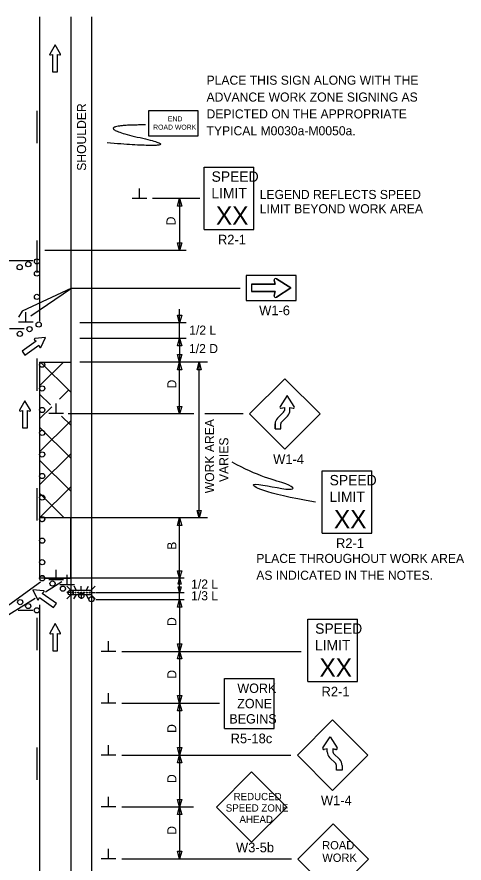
# Model space of a CAD drawing. Extents: x 16750 to 18296, y 5932 to 6919.
# Drawn here: x 17082 to 17427, y 6265 to 6918 of the extents above; entities that cross this region are included whole.
import ezdxf

# ---------------------------------------------------------------- set-up
doc = ezdxf.new("R2010")
doc.units = 0
for name, color, linetype in [('BORDER', 7, 'Continuous'), ('MT_SCRATCH_LEVEL_A', 7, 'Continuous'), ('MT_SCRATCH_LEVEL_E', 7, 'Continuous'), ('MT_STAGE_1A_NOTES', 7, 'Continuous'), ('PAVT_EDGE_EX', 7, 'Continuous'), ('TRAFFIC_SIGNS_PR', 7, 'Continuous'), ('TYPICAL_EX', 7, 'Continuous'), ('TYPICAL_TEXT_DIMEN_EX', 7, 'Continuous'), ('TYPICAL_TEXT_DIMEN_PR', 7, 'Continuous')]:
    doc.layers.add(name, color=color, linetype=linetype)

msp = doc.modelspace()

# ---------------------------------------------------------------- linework, layer by layer
at = {"layer": 'BORDER'}
msp.add_line((17123.59, 6917.57), (17123.59, 6063.18), dxfattribs=at)
at = {"layer": 'MT_SCRATCH_LEVEL_A'}
for p, q in [((17099.59, 6917.57), (17099.59, 6682.86)), ((17099.59, 6651.4), (17123.59, 6651.4)), ((17099.59, 6651.4), (17099.59, 6484.67)), ((17099.59, 6633.05), (17117.94, 6651.4)), ((17123.59, 6628.14), (17100.33, 6651.4)), ((17114.89, 6622.89), (17121.86, 6629.87)), ((17107.95, 6618.33), (17099.59, 6626.69)), ((17099.59, 6607.59), (17109.02, 6617.02)), ((17099.59, 6582.14), (17123.59, 6606.14)), ((17123.59, 6602.69), (17116.62, 6609.66)), ((17123.59, 6577.23), (17099.59, 6601.23)), ((17099.59, 6556.68), (17123.59, 6580.68)), ((17123.59, 6551.78), (17099.59, 6575.78)), ((17099.59, 6531.23), (17123.59, 6555.23)), ((17118.68, 6531.23), (17099.59, 6550.32)), ((17099.59, 6464.33), (17099.59, 6063.18))]:
    msp.add_line(p, q, dxfattribs=at)
for points in [[(17097.59, 6845.22), (17097.59, 6820.22)], [(17097.59, 6745.22), (17097.59, 6720.22)], [(17097.59, 6654.22), (17097.59, 6629.22)], [(17097.59, 6554.22), (17097.59, 6529.22)], [(17097.59, 6454.22), (17097.59, 6429.22)], [(17097.59, 6354.22), (17097.59, 6329.22)]]:
    msp.add_lwpolyline(points, dxfattribs=at)
at = {"layer": 'MT_SCRATCH_LEVEL_E'}
for p, q in [((17111.52, 6896.14), (17107.41, 6888.9)), ((17111.52, 6896.14), (17107.41, 6888.9)), ((17115.67, 6888.9), (17111.52, 6896.14)), ((17115.67, 6888.9), (17111.52, 6896.14)), ((17107.89, 6888.22), (17109.67, 6888.53)), ((17107.89, 6888.22), (17109.67, 6888.53)), ((17109.67, 6888.53), (17109.67, 6875.27)), ((17109.67, 6888.53), (17109.67, 6875.27)), ((17113.41, 6875.27), (17113.41, 6888.53)), ((17113.41, 6888.53), (17115.19, 6888.22)), ((17113.41, 6875.27), (17113.41, 6888.53)), ((17113.41, 6888.53), (17115.19, 6888.22)), ((17109.67, 6875.27), (17113.41, 6875.27)), ((17109.67, 6875.27), (17113.41, 6875.27)), ((17095.68, 6668.7), (17096.95, 6667.42)), ((17095.68, 6668.7), (17096.95, 6667.42)), ((17104.25, 6670.26), (17095.96, 6669.49)), ((17104.25, 6670.26), (17095.96, 6669.49)), ((17100.69, 6662.72), (17104.25, 6670.26)), ((17100.69, 6662.72), (17104.25, 6670.26)), ((17096.95, 6667.42), (17086.08, 6659.83)), ((17096.95, 6667.42), (17086.08, 6659.83)), ((17088.23, 6656.77), (17099.09, 6664.36)), ((17088.23, 6656.77), (17099.09, 6664.36)), ((17099.09, 6664.36), (17099.85, 6662.72)), ((17099.09, 6664.36), (17099.85, 6662.72)), ((17086.08, 6659.83), (17088.23, 6656.77)), ((17086.08, 6659.83), (17088.23, 6656.77)), ((17088.36, 6621.59), (17084.25, 6614.35)), ((17088.36, 6621.59), (17084.25, 6614.35)), ((17092.5, 6614.35), (17088.36, 6621.59)), ((17092.5, 6614.35), (17088.36, 6621.59)), ((17084.73, 6613.66), (17086.51, 6613.98)), ((17084.73, 6613.66), (17086.51, 6613.98)), ((17086.51, 6613.98), (17086.51, 6600.72)), ((17086.51, 6613.98), (17086.51, 6600.72)), ((17090.25, 6600.72), (17090.25, 6613.98)), ((17090.25, 6613.98), (17092.03, 6613.66)), ((17090.25, 6600.72), (17090.25, 6613.98)), ((17090.25, 6613.98), (17092.03, 6613.66)), ((17086.51, 6600.72), (17090.25, 6600.72)), ((17086.51, 6600.72), (17090.25, 6600.72)), ((17094.4, 6475.74), (17097.98, 6468.22)), ((17102.71, 6474.99), (17094.4, 6475.74)), ((17094.4, 6475.74), (17097.98, 6468.22)), ((17102.71, 6474.99), (17094.4, 6475.74)), ((17101.72, 6472.93), (17103, 6474.21)), ((17101.72, 6472.93), (17103, 6474.21)), ((17112.59, 6465.34), (17101.72, 6472.93)), ((17112.59, 6465.34), (17101.72, 6472.93)), ((17098.82, 6468.23), (17099.58, 6469.86)), ((17098.82, 6468.23), (17099.58, 6469.86)), ((17099.58, 6469.86), (17110.45, 6462.27)), ((17099.58, 6469.86), (17110.45, 6462.27)), ((17110.45, 6462.27), (17112.59, 6465.34)), ((17110.45, 6462.27), (17112.59, 6465.34)), ((17111.61, 6449.74), (17107.5, 6442.5)), ((17111.61, 6449.74), (17107.5, 6442.5)), ((17115.76, 6442.5), (17111.61, 6449.74)), ((17115.76, 6442.5), (17111.61, 6449.74)), ((17107.99, 6441.82), (17109.76, 6442.13)), ((17107.99, 6441.82), (17109.76, 6442.13)), ((17109.76, 6442.13), (17109.76, 6428.88)), ((17109.76, 6442.13), (17109.76, 6428.88)), ((17113.5, 6428.88), (17113.5, 6442.13)), ((17113.5, 6442.13), (17115.28, 6441.82)), ((17113.5, 6428.88), (17113.5, 6442.13)), ((17113.5, 6442.13), (17115.28, 6441.82)), ((17109.76, 6428.88), (17113.5, 6428.88)), ((17109.76, 6428.88), (17113.5, 6428.88))]:
    msp.add_line(p, q, dxfattribs=at)
for centre, start, end in [((17107.82, 6888.68), 150.42484, 279.96381), ((17107.82, 6888.68), 150.42484, 279.96381), ((17115.26, 6888.68), 260.03619, 29.77312), ((17115.26, 6888.68), 260.03619, 29.77312), ((17096.01, 6669.02), 95.35605, 224.89502), ((17096.01, 6669.02), 95.35605, 224.89502), ((17100.27, 6662.93), 204.96741, 334.70433), ((17100.27, 6662.93), 204.96741, 334.70433), ((17084.65, 6614.12), 150.42484, 279.96381), ((17084.65, 6614.12), 150.42484, 279.96381), ((17092.09, 6614.12), 260.03619, 29.77312), ((17092.09, 6614.12), 260.03619, 29.77312), ((17102.66, 6474.53), 315.10498, 84.84191), ((17102.66, 6474.53), 315.10498, 84.84191), ((17098.4, 6468.43), 205.49363, 335.0326), ((17098.4, 6468.43), 205.49363, 335.0326), ((17107.91, 6442.28), 150.42484, 279.96381), ((17107.91, 6442.28), 150.42484, 279.96381), ((17115.35, 6442.28), 260.03619, 29.77312), ((17115.35, 6442.28), 260.03619, 29.77312)]:
    msp.add_arc(centre, 0.463, start, end, dxfattribs=at)
at = {"layer": 'MT_STAGE_1A_NOTES'}
for p, q in [((17101.26, 6513.92), (17101.23, 6513.89)), ((17101.36, 6512.6), (17101.35, 6512.54))]:
    msp.add_line(p, q, dxfattribs=at)
for points in [[(17099.82, 6531.23), (17099.59, 6531.23), (17099.59, 6484.67), (17099.61, 6484.67)], [(17103.61, 6484.67), (17112.33, 6484.67), (17120.92, 6484.67), (17123.59, 6484.67), (17123.59, 6531.23), (17103.41, 6531.23)]]:
    msp.add_lwpolyline(points, dxfattribs=at)
for centre, start, end in [((17101.61, 6530.34), 153.67259, 214.93121), ((17101.61, 6530.34), 214.93121, 26.32741), ((17101.61, 6484.67), 0, 180)]:
    msp.add_arc(centre, 2, start, end, dxfattribs=at)
at = {"layer": 'PAVT_EDGE_EX'}
msp.add_line((17139.59, 6917.57), (17139.59, 6063.18), dxfattribs=at)
at = {"layer": 'TRAFFIC_SIGNS_PR'}
for p, q in [((17226.43, 6801.61), (17264.83, 6801.61)), ((17226.43, 6753.61), (17226.43, 6801.61)), ((17264.83, 6753.61), (17264.83, 6801.61)), ((17226.43, 6753.61), (17264.83, 6753.61)), ((17281.31, 6711.41), (17280.47, 6714.47)), ((17282.15, 6715.71), (17293.31, 6708.61)), ((17262.91, 6711.41), (17281.31, 6711.41)), ((17262.91, 6711.41), (17262.91, 6705.81)), ((17293.31, 6708.61), (17282.15, 6701.51)), ((17281.31, 6705.81), (17262.91, 6705.81)), ((17280.47, 6702.75), (17281.31, 6705.81)), ((17288.66, 6638.55), (17261.51, 6611.4)), ((17315.81, 6611.4), (17288.66, 6638.55)), ((17261.51, 6611.4), (17288.66, 6584.25)), ((17283, 6608.15), (17287.72, 6612.86)), ((17287.72, 6612.86), (17283, 6608.15)), ((17286.05, 6605.1), (17290.77, 6609.81)), ((17286.06, 6605.1), (17290.77, 6609.81)), ((17288.66, 6584.25), (17315.81, 6611.4)), ((17281.14, 6600.03), (17281.14, 6603.73)), ((17285.45, 6600.03), (17285.45, 6603.73)), ((17281.14, 6600.03), (17285.45, 6600.03)), ((17317.41, 6567.51), (17355.81, 6567.51)), ((17317.41, 6519.51), (17317.41, 6567.51)), ((17355.81, 6519.51), (17355.81, 6567.51)), ((17317.41, 6519.51), (17355.81, 6519.51)), ((17120.69, 6478.54), (17123.51, 6475.72)), ((17123.51, 6473.69), (17120.69, 6473.69)), ((17125.15, 6473.69), (17125.15, 6473.69)), ((17127.78, 6475.72), (17126.15, 6478.54)), ((17127.32, 6473.69), (17127.32, 6473.69)), ((17129.49, 6473.69), (17129.49, 6473.69)), ((17131.59, 6475.72), (17131.59, 6478.54)), ((17131.67, 6473.69), (17131.67, 6473.69)), ((17133.84, 6473.69), (17133.84, 6473.69)), ((17135.73, 6475.72), (17137.36, 6478.54)), ((17136.02, 6473.69), (17136.02, 6473.69)), ((17138.19, 6473.69), (17138.19, 6473.69)), ((17139.68, 6475.72), (17142.5, 6478.54)), ((17139.68, 6473.69), (17142.5, 6473.69)), ((17120.69, 6468.84), (17123.51, 6471.65)), ((17126.12, 6468.83), (17127.75, 6471.65)), ((17131.59, 6471.65), (17131.59, 6468.83)), ((17137.38, 6468.83), (17135.75, 6471.65)), ((17139.68, 6471.65), (17142.5, 6468.83)), ((17306.27, 6453.07), (17344.67, 6453.07)), ((17306.27, 6405.07), (17306.27, 6453.07)), ((17344.67, 6405.07), (17344.67, 6453.07)), ((17242.07, 6368.94), (17242.07, 6407.34)), ((17242.07, 6407.34), (17280.47, 6407.34)), ((17280.47, 6368.94), (17280.47, 6407.34)), ((17306.27, 6405.07), (17344.67, 6405.07)), ((17298.32, 6348.33), (17325.47, 6375.48)), ((17352.63, 6348.33), (17325.47, 6375.48)), ((17242.07, 6368.94), (17280.47, 6368.94)), ((17330.95, 6344.87), (17326.23, 6349.58)), ((17326.23, 6349.58), (17330.95, 6344.87)), ((17325.47, 6321.18), (17298.32, 6348.33)), ((17327.89, 6341.81), (17323.18, 6346.53)), ((17327.89, 6341.81), (17323.18, 6346.53)), ((17352.63, 6348.33), (17325.47, 6321.18)), ((17263.09, 6335.45), (17235.93, 6308.29)), ((17290.24, 6308.29), (17263.09, 6335.45)), ((17235.93, 6308.29), (17263.09, 6281.14)), ((17263.09, 6281.14), (17290.24, 6308.29)), ((17325.89, 6295.29), (17298.7, 6268.1)), ((17353.07, 6268.1), (17325.89, 6295.29)), ((17298.7, 6268.1), (17325.89, 6240.91)), ((17325.89, 6240.91), (17353.07, 6268.1))]:
    msp.add_line(p, q, dxfattribs=at)
for points in [[(17183.54, 6825.92), (17221.94, 6825.92), (17221.94, 6845.12), (17183.54, 6845.12)], [(17258.91, 6699.01), (17297.31, 6699.01), (17297.31, 6718.21), (17258.91, 6718.21)], [(17139.45, 6471.89), (17123.74, 6471.89), (17123.74, 6475.49), (17139.45, 6475.49)]]:
    msp.add_lwpolyline(points, close=True, dxfattribs=at)
for points in [[(17280.47, 6714.47), (17281.31, 6711.41), (17262.91, 6711.41), (17262.91, 6705.81), (17281.31, 6705.81), (17280.47, 6702.75)], [(17282.15, 6701.51), (17293.31, 6708.61), (17282.15, 6715.71)], [(17295.92, 6617.14), (17290.44, 6625.75), (17284.96, 6617.14)], [(17295.92, 6617.14), (17290.44, 6625.75), (17284.96, 6617.14)], [(17285.92, 6615.84), (17288.28, 6616.49), (17288.28, 6614.19)], [(17285.92, 6615.84), (17286.75, 6616.07), (17288.28, 6616.49), (17288.28, 6614.19)], [(17292.59, 6614.12), (17292.6, 6616.49), (17294.96, 6615.84)], [(17281.13, 6603.73), (17281.14, 6600.03), (17285.45, 6600.03), (17285.45, 6603.73)], [(17318.02, 6353.86), (17323.51, 6362.47), (17328.99, 6353.85)], [(17318.03, 6353.85), (17323.51, 6362.47), (17328.99, 6353.85)], [(17321.36, 6350.84), (17321.35, 6353.21), (17318.99, 6352.56)], [(17321.36, 6350.84), (17321.35, 6353.21), (17318.99, 6352.56)], [(17328.03, 6352.56), (17325.67, 6353.21), (17325.67, 6350.91)], [(17328.03, 6352.56), (17327.19, 6352.79), (17325.67, 6353.21), (17325.67, 6350.91)], [(17332.81, 6340.45), (17332.81, 6336.75), (17328.5, 6336.75), (17328.5, 6340.45)]]:
    msp.add_lwpolyline(points, dxfattribs=at)
for centre, radius in [((17090.92, 6726.9), 2), ((17097.59, 6729.05), 2), ((17084.26, 6724.59), 2), ((17097.59, 6719.69), 2), ((17097.59, 6701.69), 2), ((17098.93, 6680.39), 2), ((17084.45, 6673.15), 2), ((17091.88, 6676.87), 2), ((17101.61, 6649.4), 2), ((17101.61, 6631.09), 2), ((17101.61, 6614.48), 2), ((17101.61, 6596.79), 2), ((17101.61, 6580.18), 2), ((17101.61, 6563.56), 2), ((17101.61, 6546.95), 2), ((17101.61, 6530.34), 2), ((17101.61, 6513.73), 2), ((17101.61, 6497.12), 2), ((17101.61, 6484.67), 2), ((17109.61, 6480.67), 2), ((17117.61, 6476.67), 2), ((17123.59, 6473.69), 2), ((17125.17, 6473.69), 0.379), ((17127.32, 6473.69), 0.379), ((17129.49, 6473.69), 0.379), ((17131.81, 6471.27), 2), ((17131.67, 6473.69), 0.379), ((17133.84, 6473.69), 0.379), ((17136.01, 6473.69), 0.379), ((17138.19, 6473.69), 0.379), ((17084.65, 6466.32), 2), ((17139.57, 6468.56), 2), ((17090.87, 6463.28), 2), ((17097.46, 6460), 2)]:
    msp.add_circle(centre, radius, dxfattribs=at)
for centre, radius, start, end in [((17281.55, 6714.76), 1.12, 57.53038, 195.32692), ((17281.55, 6714.76), 1.12, 57.53038, 195.32692), ((17281.55, 6702.45), 1.12, 164.67308, 302.46962), ((17281.55, 6702.45), 1.12, 164.67308, 302.46963), ((17285.69, 6616.67), 0.864, 147.52044, 285.3986), ((17285.69, 6616.67), 0.866, 147.52881, 285.38519), ((17295.19, 6616.68), 0.866, 254.67989, 32.28036), ((17286.43, 6614.19), 1.85, 314.21254, 0), ((17286.43, 6614.19), 1.85, 314.2123, 0.1238), ((17286.43, 6614.19), 6.17, 314.21254, 359.38189), ((17286.43, 6614.19), 6.17, 314.76872, 359.37555), ((17287.3, 6603.73), 6.17, 134.21254, 180), ((17287.3, 6603.73), 6.17, 134.21254, 180), ((17287.3, 6603.73), 6.17, 134.21172, 180), ((17287.3, 6603.73), 1.85, 132.37199, 180), ((17287.3, 6603.73), 1.85, 134.21254, 180), ((17318.76, 6353.39), 0.866, 147.7292, 285.31719), ((17318.76, 6353.39), 0.866, 147.71964, 285.32011), ((17308.91, 6359.65), 10.8, 327.53351, 327.54311), ((17321.84, 6342.14), 10.8, 105.31922, 105.32004), ((17327.52, 6350.91), 6.17, 180.61811, 225.78746), ((17327.52, 6350.91), 6.17, 180.62445, 225.23128), ((17327.52, 6350.91), 1.85, 180, 225.78746), ((17327.52, 6350.91), 1.85, 179.8762, 225.7877), ((17328.26, 6353.39), 0.866, 254.61481, 32.47119), ((17326.64, 6340.45), 6.17, 0, 45.78828), ((17326.64, 6340.45), 1.85, 0, 47.62801)]:
    msp.add_arc(centre, radius, start, end, dxfattribs=at)
msp.add_open_spline([(17181.19, 6834.28), (17133.95, 6834.28), (17218.98, 6814.94), (17151.64, 6820.43)], degree=2, dxfattribs=at)
at = {"layer": 'TYPICAL_EX'}
for p, q in [((17176.71, 6777.47), (17176.71, 6785.26)), ((17182.34, 6777.47), (17171.09, 6777.47)), ((17088.96, 6682.12), (17088.96, 6689.91)), ((17094.59, 6682.12), (17083.34, 6682.12)), ((17087.66, 6677.17), (17076.41, 6677.17)), ((17112.33, 6611.74), (17112.33, 6619.53)), ((17117.95, 6611.74), (17106.7, 6611.74)), ((17112.33, 6483.42), (17112.33, 6491.2)), ((17120.92, 6479.56), (17120.92, 6487.34)), ((17117.95, 6483.42), (17106.7, 6483.42)), ((17126.55, 6479.56), (17115.3, 6479.56)), ((17152.71, 6428.36), (17152.71, 6436.14)), ((17158.34, 6428.36), (17147.09, 6428.36)), ((17152.71, 6388.36), (17152.71, 6396.14)), ((17158.34, 6388.36), (17147.09, 6388.36)), ((17152.71, 6348.36), (17152.71, 6356.14)), ((17158.34, 6348.36), (17147.09, 6348.36)), ((17152.71, 6308.36), (17152.71, 6316.14)), ((17158.34, 6308.36), (17147.09, 6308.36)), ((17152.71, 6268.36), (17152.71, 6276.14)), ((17158.34, 6268.36), (17147.09, 6268.36))]:
    msp.add_line(p, q, dxfattribs=at)
at = {"layer": 'TYPICAL_TEXT_DIMEN_PR'}
for p, q in [((17223.13, 6777.47), (17186.59, 6777.47)), ((17206.02, 6771.61), (17207.59, 6777.47)), ((17207.59, 6777.47), (17209.16, 6771.61)), ((17207.59, 6777.47), (17207.59, 6737.47)), ((17207.59, 6771.61), (17206.02, 6771.61)), ((17209.16, 6771.61), (17207.59, 6771.61)), ((17207.59, 6737.47), (17206.02, 6743.34)), ((17206.02, 6743.34), (17207.59, 6743.34)), ((17207.59, 6737.47), (17206.02, 6743.34)), ((17206.02, 6743.34), (17207.59, 6743.34)), ((17207.59, 6743.34), (17209.16, 6743.34)), ((17209.16, 6743.34), (17207.59, 6737.47)), ((17207.59, 6743.34), (17209.16, 6743.34)), ((17209.16, 6743.34), (17207.59, 6737.47)), ((17212.59, 6737.47), (17103.65, 6737.47)), ((16962.49, 6729.72), (17094.41, 6729.72)), ((17124.22, 6708.37), (17086.08, 6690.64)), ((17092.76, 6687.09), (17124.22, 6708.37)), ((17124.22, 6708.37), (17254.22, 6708.37)), ((17086.08, 6690.64), (17083.35, 6686)), ((17207.59, 6669.72), (17207.59, 6692.26)), ((17212.59, 6681.72), (17130.55, 6681.72)), ((17207.59, 6681.72), (17206.02, 6687.58)), ((17206.02, 6687.58), (17207.59, 6687.58)), ((17207.59, 6687.58), (17209.16, 6687.58)), ((17209.16, 6687.58), (17207.59, 6681.72)), ((17212.59, 6669.72), (17130.55, 6669.72)), ((17206.02, 6663.86), (17207.59, 6669.72)), ((17207.59, 6669.72), (17209.16, 6663.86)), ((17207.59, 6669.72), (17207.59, 6651.4)), ((17207.59, 6663.86), (17206.02, 6663.86)), ((17209.16, 6663.86), (17207.59, 6663.86)), ((17207.59, 6651.4), (17206.02, 6657.26)), ((17206.02, 6657.26), (17207.59, 6657.26)), ((17207.59, 6657.26), (17209.16, 6657.26)), ((17209.16, 6657.26), (17207.59, 6651.4)), ((17229.13, 6651.4), (17130.55, 6651.4)), ((17206.02, 6645.54), (17207.59, 6651.4)), ((17207.59, 6611.4), (17207.59, 6651.4)), ((17207.59, 6651.4), (17209.16, 6645.54)), ((17221.02, 6645.54), (17222.59, 6651.4)), ((17222.59, 6531.23), (17222.59, 6651.4)), ((17222.59, 6651.4), (17224.16, 6645.54)), ((17207.59, 6645.54), (17206.02, 6645.54)), ((17209.16, 6645.54), (17207.59, 6645.54)), ((17222.59, 6645.54), (17221.02, 6645.54)), ((17224.16, 6645.54), (17222.59, 6645.54)), ((17207.59, 6611.4), (17206.02, 6617.26)), ((17206.02, 6617.26), (17207.59, 6617.26)), ((17207.59, 6617.26), (17209.16, 6617.26)), ((17209.16, 6617.26), (17207.59, 6611.4)), ((17218.42, 6611.4), (17121.69, 6611.4)), ((17256.51, 6611.4), (17226.95, 6611.4)), ((17222.59, 6531.23), (17221.02, 6537.09)), ((17221.02, 6537.09), (17222.59, 6537.09)), ((17222.59, 6537.09), (17224.16, 6537.09)), ((17224.16, 6537.09), (17222.59, 6531.23)), ((17123.59, 6531.23), (17099.59, 6531.23)), ((17229.13, 6531.23), (17124.58, 6531.23)), ((17206.02, 6525.36), (17207.59, 6531.23)), ((17207.59, 6525.36), (17206.02, 6525.36)), ((17207.59, 6468.36), (17207.59, 6531.23)), ((17207.59, 6531.23), (17209.16, 6525.36)), ((17209.16, 6525.36), (17207.59, 6525.36)), ((17207.59, 6480.36), (17207.59, 6499.17)), ((17207.59, 6484.67), (17206.02, 6490.54)), ((17206.02, 6490.54), (17207.59, 6490.54)), ((17207.59, 6490.54), (17209.16, 6490.54)), ((17209.16, 6490.54), (17207.59, 6484.67)), ((17003.97, 6412.5), (17100.41, 6482.06)), ((17123.59, 6484.67), (17099.6, 6484.67)), ((17104.05, 6474.28), (17116.73, 6482.11)), ((17211.07, 6484.67), (17124.58, 6484.67)), ((17206.41, 6480.28), (17207.59, 6484.67)), ((17207.59, 6480.28), (17206.41, 6480.28)), ((17207.59, 6484.67), (17208.77, 6480.28)), ((17208.77, 6480.28), (17207.59, 6480.28)), ((17142.93, 6473.69), (17211.14, 6473.69)), ((17207.59, 6473.69), (17206.41, 6478.08)), ((17206.41, 6478.08), (17207.59, 6478.08)), ((17207.59, 6478.08), (17208.77, 6478.08)), ((17208.77, 6478.08), (17207.59, 6473.69)), ((17003.97, 6412.5), (17096.28, 6469.48)), ((17142.93, 6468.36), (17211.14, 6468.36)), ((17206.02, 6462.49), (17207.59, 6468.36)), ((17207.59, 6468.36), (17207.59, 6428.36)), ((17207.59, 6468.36), (17209.16, 6462.49)), ((17083.12, 6460), (17094.47, 6460)), ((17207.59, 6462.49), (17206.02, 6462.49)), ((17209.16, 6462.49), (17207.59, 6462.49)), ((17207.59, 6428.36), (17206.02, 6434.22)), ((17206.02, 6434.22), (17207.59, 6434.22)), ((17207.59, 6434.22), (17209.16, 6434.22)), ((17209.16, 6434.22), (17207.59, 6428.36)), ((17162.94, 6428.36), (17301.31, 6428.36)), ((17206.02, 6422.49), (17207.59, 6428.36)), ((17207.59, 6428.36), (17207.59, 6388.36)), ((17207.59, 6428.36), (17209.16, 6422.49)), ((17207.59, 6422.49), (17206.02, 6422.49)), ((17209.16, 6422.49), (17207.59, 6422.49)), ((17162.94, 6388.36), (17238.21, 6388.36)), ((17207.59, 6388.36), (17206.02, 6394.22)), ((17206.02, 6394.22), (17207.59, 6394.22)), ((17206.02, 6382.49), (17207.59, 6388.36)), ((17207.59, 6394.22), (17209.16, 6394.22)), ((17209.16, 6394.22), (17207.59, 6388.36)), ((17207.59, 6388.36), (17207.59, 6348.36)), ((17207.59, 6388.36), (17209.16, 6382.49)), ((17207.59, 6382.49), (17206.02, 6382.49)), ((17209.16, 6382.49), (17207.59, 6382.49)), ((17207.59, 6348.36), (17206.02, 6354.22)), ((17206.02, 6354.22), (17207.59, 6354.22)), ((17207.59, 6354.22), (17209.16, 6354.22)), ((17209.16, 6354.22), (17207.59, 6348.36)), ((17162.94, 6348.36), (17293.32, 6348.36)), ((17206.02, 6342.49), (17207.59, 6348.36)), ((17207.59, 6342.49), (17206.02, 6342.49)), ((17207.59, 6348.36), (17207.59, 6308.36)), ((17207.59, 6348.36), (17209.16, 6342.49)), ((17209.16, 6342.49), (17207.59, 6342.49)), ((17207.59, 6308.36), (17206.02, 6314.22)), ((17206.02, 6314.22), (17207.59, 6314.22)), ((17207.59, 6314.22), (17209.16, 6314.22)), ((17209.16, 6314.22), (17207.59, 6308.36)), ((17162.94, 6308.36), (17218.15, 6308.36)), ((17206.02, 6302.49), (17207.59, 6308.36)), ((17207.59, 6308.36), (17207.59, 6268.36)), ((17207.59, 6308.36), (17209.16, 6302.49)), ((17207.59, 6302.49), (17206.02, 6302.49)), ((17209.16, 6302.49), (17207.59, 6302.49)), ((17207.59, 6268.36), (17206.02, 6274.22)), ((17206.02, 6274.22), (17207.59, 6274.22)), ((17207.59, 6274.22), (17209.16, 6274.22)), ((17209.16, 6274.22), (17207.59, 6268.36)), ((17162.94, 6268.36), (17293.7, 6268.36))]:
    msp.add_line(p, q, dxfattribs=at)
msp.add_open_spline([(17312.25, 6543.5), (17272.08, 6550.01), (17252.37, 6561.87), (17296.82, 6550.62), (17296.82, 6556.77), (17267.09, 6563.45), (17248.02, 6574.25)], degree=3, dxfattribs=at)

# ---------------------------------------------------------------- texts
at = {"layer": 'TRAFFIC_SIGNS_PR'}
for s, height, p in [('PLACE THIS SIGN ALONG WITH THE', 7, (17228.3, 6865.29)), ('ADVANCE WORK ZONE SIGNING AS', 7, (17228.3, 6852.29)), ('DEPICTED ON THE APPROPRIATE', 7, (17228.3, 6839.29)), ('END', 3.831, (17198.54, 6837.05)), ('ROAD WORK', 3.831, (17187.15, 6830.66)), ('TYPICAL M0030a-M0050a.', 7, (17228.3, 6826.29)), ('SPEED', 8, (17232.2, 6790.47)), ('LIMIT', 8, (17232.04, 6777.67)), ('LEGEND REFLECTS SPEED', 7, (17269.3, 6777.15)), ('LIMIT BEYOND WORK AREA', 7, (17269.3, 6766.15)), ('XX', 14.031, (17235.55, 6757.36)), ('R2-1', 7.44, (17237.11, 6742.17)), ('W1-6', 7.44, (17268.85, 6687.57)), ('W1-4', 7.44, (17279.66, 6572.81)), ('SPEED', 8, (17323.18, 6556.37)), ('LIMIT', 8, (17323.02, 6543.57)), ('XX', 14.031, (17326.53, 6523.26)), ('R2-1', 7.44, (17328.09, 6508.07)), ('PLACE THROUGHOUT WORK AREA', 7, (17266.66, 6496.52)), ('AS INDICATED IN THE NOTES.', 7, (17266.66, 6483.52)), ('SPEED', 8, (17312.04, 6441.93)), ('LIMIT', 8, (17311.88, 6429.13)), ('XX', 14.031, (17315.39, 6408.83)), ('WORK', 7.217, (17252.07, 6396.31)), ('R2-1', 7.44, (17316.95, 6393.63)), ('ZONE', 7.217, (17251.95, 6384.49)), ('BEGINS', 7.217, (17245.88, 6372.69)), ('R5-18c', 7.44, (17246.88, 6357.5)), ('REDUCED', 5.6, (17249.15, 6313.6)), ('W1-4', 7.44, (17316.48, 6309.74)), ('SPEED ZONE', 5.6, (17243.14, 6304.8)), ('AHEAD', 5.6, (17253.7, 6296)), ('W3-5b', 7.44, (17251.04, 6273.4)), ('ROAD', 6.408, (17317.42, 6275.64)), ('WORK', 6.408, (17317.53, 6266.03))]:
    msp.add_text(s, height=height, dxfattribs=at).set_placement(p)
at = {"layer": 'TYPICAL_TEXT_DIMEN_EX'}
msp.add_text('SHOULDER', height=7, rotation=90, dxfattribs=at).set_placement((17135.45, 6798.95))
at = {"layer": 'TYPICAL_TEXT_DIMEN_PR'}
for s, p in [('D', (17204.39, 6756.88)), ('D', (17205.03, 6631.09)), ('WORK AREA', (17234.14, 6550.27)), ('VARIES', (17245.14, 6558.91)), ('B', (17205.03, 6506.65)), ('D', (17205.03, 6447.91)), ('D', (17205.03, 6407.24)), ('D', (17205.03, 6365.47)), ('D', (17205.03, 6326.81)), ('D', (17205.03, 6286.92))]:
    msp.add_text(s, height=7, rotation=90, dxfattribs=at).set_placement(p)
for s, p in [('1/2 L', (17214.94, 6672.55)), ('1/2 D', (17214.8, 6658.32)), ('1/2 L', (17216.41, 6476.72)), ('1/3 L', (17216.41, 6467.72))]:
    msp.add_text(s, height=7, dxfattribs=at).set_placement(p)

doc.saveas('drawing.dxf')
